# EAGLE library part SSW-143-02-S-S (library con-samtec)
THROUGH-HOLE .025" SQ POST SOCKET Source: Samtec SSW.pdf
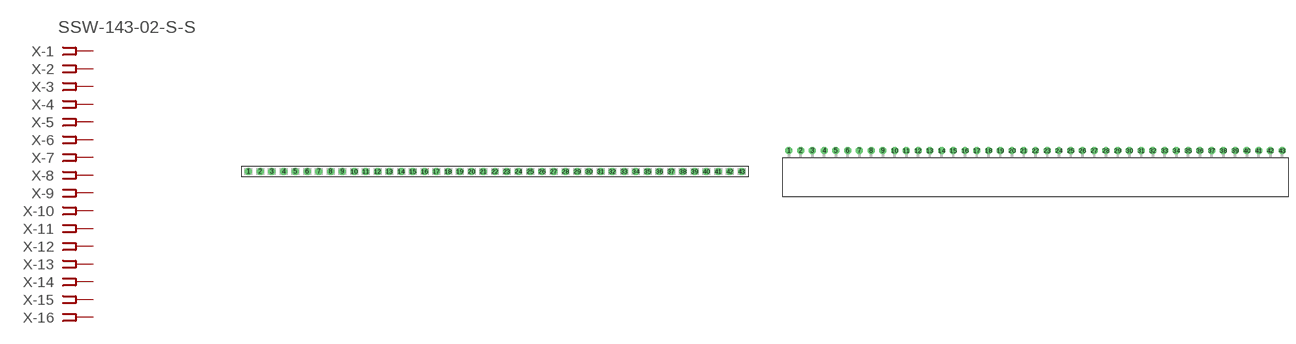
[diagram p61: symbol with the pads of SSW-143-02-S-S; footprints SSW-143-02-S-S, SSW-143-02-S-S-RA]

Designator prefix X; gates -1=FPINV -2=FPIN -3=FPIN -4=FPIN -5=FPIN -6=FPIN -7=FPIN -8=FPIN -9=FPIN -10=FPIN -11=FPIN -12=FPIN -13=FPIN -14=FPIN -15=FPIN -16=FPIN -17=FPIN -18=FPIN -19=FPIN -20=FPIN -21=FPIN -22=FPIN -23=FPIN -24=FPIN -25=FPIN -26=FPIN -27=FPIN -28=FPIN -29=FPIN -30=FPIN -31=FPIN -32=FPIN -33=FPIN -34=FPIN -35=FPIN -36=FPIN -37=FPIN -38=FPIN -39=FPIN -40=FPIN -41=FPIN -42=FPIN -43=FPIN

## SSW-143-02-S-S (OC_FARNELL: unknown; OC_NEWARK: unknown)  [SSW-143-02-S-S]
1  -1:1  pas
2  -2:1  pas
3  -3:1  pas
4  -4:1  pas
5  -5:1  pas
6  -6:1  pas
7  -7:1  pas
8  -8:1  pas
9  -9:1  pas
10  -10:1  pas
11  -11:1  pas
12  -12:1  pas
13  -13:1  pas
14  -14:1  pas
15  -15:1  pas
16  -16:1  pas
17  -17:1  pas
18  -18:1  pas
19  -19:1  pas
20  -20:1  pas
21  -21:1  pas
22  -22:1  pas
23  -23:1  pas
24  -24:1  pas
25  -25:1  pas
26  -26:1  pas
27  -27:1  pas
28  -28:1  pas
29  -29:1  pas
30  -30:1  pas
31  -31:1  pas
32  -32:1  pas
33  -33:1  pas
34  -34:1  pas
35  -35:1  pas
36  -36:1  pas
37  -37:1  pas
38  -38:1  pas
39  -39:1  pas
40  -40:1  pas
41  -41:1  pas
42  -42:1  pas
43  -43:1  pas

## SSW-143-02-S-S-RA (OC_FARNELL: unknown; OC_NEWARK: unknown)  [SSW-143-02-S-S-RA]
Pads as for SSW-143-02-S-S

## Footprint SSW-143-02-S-S (pad centres in mm)
THROUGH-HOLE .025" SQ POST SOCKET Source: Samtec SSW.pdf
drill 1 pad 1.5 octagon: 1 -53.34,0; 2 -50.8,0; 3 -48.26,0; 4 -45.72,0; 5 -43.18,0; 6 -40.64,0; 7 -38.1,0; 8 -35.56,0; 9 -33.02,0; 10 -30.48,0; 11 -27.94,0; 12 -25.4,0; 13 -22.86,0; 14 -20.32,0; 15 -17.78,0; 16 -15.24,0; 17 -12.7,0; 18 -10.16,0; 19 -7.62,0; 20 -5.08,0; 21 -2.54,0; 22 0,0; 23 2.54,0; 24 5.08,0; 25 7.62,0; 26 10.16,0; 27 12.7,0; 28 15.24,0; 29 17.78,0; 30 20.32,0; 31 22.86,0; 32 25.4,0; 33 27.94,0; 34 30.48,0; 35 33.02,0; 36 35.56,0; 37 38.1,0; 38 40.64,0; 39 43.18,0; 40 45.72,0; 41 48.26,0; 42 50.8,0; 43 53.34,0

## Footprint SSW-143-02-S-S-RA (pad centres in mm)
THROUGH-HOLE .025" SQ POST SOCKET Source: Samtec SSW.pdf
drill 1 pad 1.5 octagon: 1 -53.34,1.524; 2 -50.8,1.524; 3 -48.26,1.524; 4 -45.72,1.524; 5 -43.18,1.524; 6 -40.64,1.524; 7 -38.1,1.524; 8 -35.56,1.524; 9 -33.02,1.524; 10 -30.48,1.524; 11 -27.94,1.524; 12 -25.4,1.524; 13 -22.86,1.524; 14 -20.32,1.524; 15 -17.78,1.524; 16 -15.24,1.524; 17 -12.7,1.524; 18 -10.16,1.524; 19 -7.62,1.524; 20 -5.08,1.524; 21 -2.54,1.524; 22 0,1.524; 23 2.54,1.524; 24 5.08,1.524; 25 7.62,1.524; 26 10.16,1.524; 27 12.7,1.524; 28 15.24,1.524; 29 17.78,1.524; 30 20.32,1.524; 31 22.86,1.524; 32 25.4,1.524; 33 27.94,1.524; 34 30.48,1.524; 35 33.02,1.524; 36 35.56,1.524; 37 38.1,1.524; 38 40.64,1.524; 39 43.18,1.524; 40 45.72,1.524; 41 48.26,1.524; 42 50.8,1.524; 43 53.34,1.524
